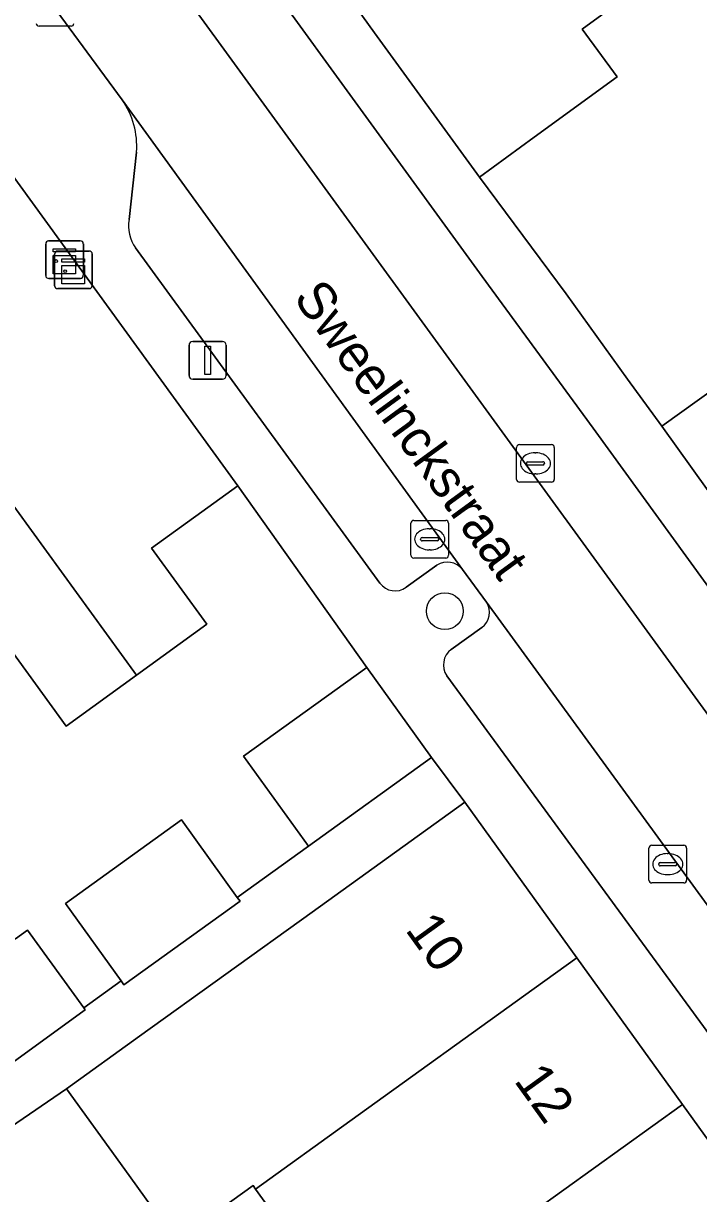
# Model space of a CAD drawing. Extents: x 159817 to 160765, y 380688 to 381638.
# Drawn here: x 159986.43 to 160004.37, y 381261.64 to 381292.74 of the extents above; entities that cross this region are included whole.
import ezdxf

# ---------------------------------------------------------------- set-up
doc = ezdxf.new("R2010")
doc.units = 0
for name, color, linetype in [('IMGEO_Boom', 7, 'Continuous'), ('IMGEO_Erf', 7, 'Continuous'), ('IMGEO_Kast', 7, 'Continuous'), ('IMGEO_Kolk', 7, 'Continuous'), ('IMGEO_Lichtmast', 7, 'Continuous'), ('IMGEO_Muur', 7, 'Continuous'), ('IMGEO_Openbare_ruimte_label', 7, 'Continuous'), ('IMGEO_Pand', 7, 'Continuous'), ('IMGEO_Pand_nummerreeks', 7, 'Continuous'), ('IMGEO_Parkeervlak_open', 7, 'Continuous'), ('IMGEO_Rijbaan_lokaal_open', 7, 'Continuous'), ('IMGEO_Voetpad_open', 7, 'Continuous')]:
    doc.layers.add(name, color=color, linetype=linetype)

msp = doc.modelspace()

# ---------------------------------------------------------------- linework, layer by layer
at = {"layer": 'IMGEO_Boom'}
msp.add_circle((159997.629, 381277.121), 0.489, dxfattribs=at)
at = {"layer": 'IMGEO_Erf'}
for points in [[(160003.758, 381294.399), (160001.277, 381292.589), (160002.202, 381291.321), (160000, 381289.714), (159998.551, 381288.656), (160000.854, 381285.557), (160002.484, 381283.284), (160003.391, 381282.036), (160007.455, 381284.95), (160011.43, 381287.801), (160011.887, 381288.128), (160013.409, 381286.006), (160015.435, 381287.459), (160016.713, 381285.677), (160019.191, 381287.455)], [(159986.225, 381268.414), (159986.544, 381268.646), (159988.034, 381266.576), (159989.03, 381267.293), (159987.548, 381269.352), (159990.632, 381271.572), (159992.114, 381269.514), (159994.006, 381270.876), (159992.283, 381273.269), (159995.552, 381275.622), (159992.128, 381280.454), (159989.838, 381278.792), (159991.302, 381276.775), (159989.435, 381275.42), (159987.567, 381274.065), (159986.123, 381276.055)], [(159993.924, 381259.923), (159992.602, 381261.76), (159992.535, 381261.853), (159990.492, 381260.382), (159989.123, 381262.284), (159987.58, 381264.428), (159980.467, 381259.561)]]:
    msp.add_lwpolyline(points, dxfattribs=at)
at = {"layer": 'IMGEO_Kast'}
for p, q in [((159987.025, 381286.036), (159987.025, 381286.877)), ((159987.025, 381286.877), (159987.025, 381286.036)), ((159987.1, 381286.961), (159987.941, 381286.961)), ((159987.941, 381286.961), (159987.1, 381286.961)), ((159987.338, 381286.691), (159988.179, 381286.691)), ((159988.179, 381286.691), (159987.338, 381286.691)), ((159988.025, 381286.886), (159988.025, 381286.045)), ((159988.025, 381286.045), (159988.025, 381286.886)), ((159987.263, 381285.766), (159987.263, 381286.607)), ((159987.263, 381286.607), (159987.263, 381285.766)), ((159988.263, 381286.616), (159988.263, 381285.775)), ((159988.263, 381285.775), (159988.263, 381286.616)), ((159987.95, 381285.961), (159987.109, 381285.961)), ((159987.109, 381285.961), (159987.95, 381285.961)), ((159988.188, 381285.691), (159987.347, 381285.691)), ((159987.347, 381285.691), (159988.188, 381285.691))]:
    msp.add_line(p, q, dxfattribs=at)
for points in [[(159987.22, 381286.751), (159987.82, 381286.751), (159987.82, 381286.666), (159987.22, 381286.666), (159987.22, 381286.751)], [(159987.22, 381286.576), (159987.82, 381286.576), (159987.82, 381286.087), (159987.22, 381286.087), (159987.22, 381286.576)], [(159987.458, 381286.481), (159988.058, 381286.481), (159988.058, 381286.396), (159987.458, 381286.396), (159987.458, 381286.481)], [(159987.458, 381286.306), (159988.058, 381286.306), (159988.058, 381285.817), (159987.458, 381285.817), (159987.458, 381286.306)]]:
    msp.add_lwpolyline(points, dxfattribs=at)
for centre in [(159987.304, 381286.425), (159987.542, 381286.155)]:
    msp.add_circle(centre, 0.0377, dxfattribs=at)
for centre, start, end in [((159987.103, 381286.883), 92.4484, 184.2845), ((159987.103, 381286.883), 92.4484, 184.2845), ((159987.341, 381286.613), 92.4484, 184.2845), ((159987.341, 381286.613), 92.4484, 184.2845), ((159987.947, 381286.883), 2.4484, 94.2845), ((159987.947, 381286.883), 2.4484, 94.2845), ((159988.185, 381286.613), 2.4484, 94.2845), ((159988.185, 381286.613), 2.4484, 94.2845), ((159987.947, 381286.039), 272.4484, 4.2845), ((159987.947, 381286.039), 272.4484, 4.2845), ((159987.103, 381286.039), 182.4484, 274.2845), ((159987.103, 381286.039), 182.4484, 274.2845), ((159987.341, 381285.769), 182.4484, 274.2845), ((159987.341, 381285.769), 182.4484, 274.2845), ((159988.185, 381285.769), 272.4484, 4.2845), ((159988.185, 381285.769), 272.4484, 4.2845)]:
    msp.add_arc(centre, 0.0779, start, end, dxfattribs=at)
at = {"layer": 'IMGEO_Kolk'}
for p, q in [((159987.7, 381292.666), (159986.848, 381292.666)), ((159999.535, 381280.621), (159999.535, 381281.473)), ((159999.61, 381281.547), (160000.462, 381281.547)), ((160000.536, 381281.473), (160000.536, 381280.621)), ((159999.837, 381281.09), (160000.235, 381281.09)), ((160000.023, 381281.327), (160000.048, 381281.327)), ((159999.794, 381281.041), (159999.794, 381281.053)), ((160000.232, 381281.004), (159999.834, 381281.004)), ((160000.046, 381280.767), (160000.021, 381280.767)), ((160000.278, 381281.053), (160000.278, 381281.041)), ((160000.462, 381280.547), (159999.61, 381280.547)), ((159996.8, 381279.531), (159997.652, 381279.531)), ((159996.725, 381278.605), (159996.725, 381279.457)), ((159997.213, 381279.311), (159997.238, 381279.311)), ((159997.726, 381279.457), (159997.726, 381278.605)), ((159996.984, 381279.025), (159996.984, 381279.037)), ((159997.422, 381278.988), (159997.024, 381278.988)), ((159997.027, 381279.074), (159997.425, 381279.074)), ((159997.468, 381279.037), (159997.468, 381279.025)), ((159997.236, 381278.751), (159997.211, 381278.751)), ((159997.652, 381278.531), (159996.8, 381278.531)), ((160003.05, 381269.971), (160003.05, 381270.823)), ((160003.125, 381270.897), (160003.977, 381270.897)), ((160004.051, 381270.823), (160004.051, 381269.971)), ((160003.538, 381270.677), (160003.563, 381270.677)), ((160003.309, 381270.391), (160003.309, 381270.403)), ((160003.747, 381270.354), (160003.349, 381270.354)), ((160003.352, 381270.44), (160003.75, 381270.44)), ((160003.793, 381270.403), (160003.793, 381270.391)), ((160003.977, 381269.897), (160003.125, 381269.897)), ((160003.561, 381270.117), (160003.536, 381270.117))]:
    msp.add_line(p, q, dxfattribs=at)
for points in [[(159987.7, 381292.666), (159986.848, 381292.666)], [(159999.535, 381280.621), (159999.535, 381281.473)], [(159999.61, 381281.547), (160000.462, 381281.547)], [(160000.536, 381281.473), (160000.536, 381280.621)], [(160000.462, 381280.547), (159999.61, 381280.547)], [(159996.8, 381279.531), (159997.652, 381279.531)], [(159996.725, 381278.605), (159996.725, 381279.457)], [(159997.726, 381279.457), (159997.726, 381278.605)], [(159997.652, 381278.531), (159996.8, 381278.531)], [(160003.05, 381269.971), (160003.05, 381270.823)], [(160003.125, 381270.897), (160003.977, 381270.897)], [(160004.051, 381270.823), (160004.051, 381269.971)], [(160003.977, 381269.897), (160003.125, 381269.897)]]:
    msp.add_lwpolyline(points, dxfattribs=at)
for centre, radius, start, end in [((159986.85, 381292.742), 0.0765, 181.552, 268.448), ((159986.85, 381292.742), 0.0765, 181.552, 268.448), ((159987.698, 381292.742), 0.0765, 271.552, 358.448), ((159987.698, 381292.742), 0.0765, 271.552, 358.448), ((159999.612, 381281.471), 0.0765, 91.552, 178.448), ((159999.612, 381281.471), 0.0765, 91.552, 178.448), ((160000.46, 381281.471), 0.0765, 1.552, 88.448), ((160000.46, 381281.471), 0.0765, 1.552, 88.448), ((159999.834, 381281.05), 0.0403, 85.8775, 175.7526), ((160000.239, 381281.052), 0.0386, 1.7309, 96.639), ((159999.831, 381281.04), 0.0366, 178.938, 274.7102), ((160000.235, 381281.047), 0.043, 264.8664, 352.4533), ((159999.612, 381280.623), 0.0765, 181.552, 268.448), ((159999.612, 381280.623), 0.0765, 181.552, 268.448), ((160000.46, 381280.623), 0.0765, 271.552, 358.448), ((160000.46, 381280.623), 0.0765, 271.552, 358.448), ((159996.802, 381279.455), 0.0765, 91.552, 178.448), ((159996.802, 381279.455), 0.0765, 91.552, 178.448), ((159997.65, 381279.455), 0.0765, 1.552, 88.448), ((159997.65, 381279.455), 0.0765, 1.552, 88.448), ((159997.024, 381279.034), 0.0403, 85.8775, 175.7526), ((159997.021, 381279.024), 0.0366, 178.938, 274.7102), ((159997.425, 381279.031), 0.043, 264.8664, 352.4533), ((159997.429, 381279.036), 0.0386, 1.7309, 96.639), ((159996.802, 381278.607), 0.0765, 181.552, 268.448), ((159996.802, 381278.607), 0.0765, 181.552, 268.448), ((159997.65, 381278.607), 0.0765, 271.552, 358.448), ((159997.65, 381278.607), 0.0765, 271.552, 358.448), ((160003.127, 381270.821), 0.0765, 91.552, 178.448), ((160003.127, 381270.821), 0.0765, 91.552, 178.448), ((160003.975, 381270.821), 0.0765, 1.552, 88.448), ((160003.975, 381270.821), 0.0765, 1.552, 88.448), ((160003.349, 381270.4), 0.0403, 85.8775, 175.7526), ((160003.346, 381270.39), 0.0366, 178.938, 274.7102), ((160003.75, 381270.397), 0.043, 264.8664, 352.4533), ((160003.754, 381270.402), 0.0386, 1.7309, 96.639), ((160003.127, 381269.973), 0.0765, 181.552, 268.448), ((160003.127, 381269.973), 0.0765, 181.552, 268.448), ((160003.975, 381269.973), 0.0765, 271.552, 358.448), ((160003.975, 381269.973), 0.0765, 271.552, 358.448)]:
    msp.add_arc(centre, radius, start, end, dxfattribs=at)
for centre, major_axis, ratio, start_param, end_param in [((160000.022, 381281.047), (-0.387, 0.002), 0.722429, 4.712389, 7.853982), ((160000.047, 381281.047), (-0.39, 0.002), 0.717154, 1.570796, 4.712389), ((159997.212, 381279.031), (-0.387, 0.002), 0.722429, 4.712389, 7.853982), ((159997.237, 381279.031), (-0.39, 0.002), 0.717154, 1.570796, 4.712389), ((160003.537, 381270.397), (-0.387, 0.002), 0.722429, 4.712389, 7.853982), ((160003.562, 381270.397), (-0.39, 0.002), 0.717154, 1.570796, 4.712389)]:
    msp.add_ellipse(centre, major_axis=major_axis, ratio=ratio, start_param=start_param, end_param=end_param, dxfattribs=at)
at = {"layer": 'IMGEO_Lichtmast'}
for p, q in [((159990.832, 381283.386), (159990.832, 381284.186)), ((159990.832, 381284.186), (159990.832, 381283.386)), ((159990.932, 381284.286), (159991.722, 381284.286)), ((159991.722, 381284.286), (159990.932, 381284.286)), ((159991.822, 381284.186), (159991.822, 381283.386)), ((159991.822, 381283.386), (159991.822, 381284.186)), ((159991.722, 381283.286), (159990.932, 381283.286)), ((159990.932, 381283.286), (159991.722, 381283.286))]:
    msp.add_line(p, q, dxfattribs=at)
msp.add_lwpolyline([(159991.252, 381284.161), (159991.402, 381284.161), (159991.402, 381283.411), (159991.252, 381283.411), (159991.252, 381284.161)], dxfattribs=at)
for centre, start, end in [((159990.932, 381284.186), 90, 180), ((159990.932, 381284.186), 90, 180), ((159991.722, 381284.186), 0, 90), ((159991.722, 381284.186), 360, 90), ((159990.932, 381283.386), 180, 270), ((159990.932, 381283.386), 180, 270), ((159991.722, 381283.386), 270, 0), ((159991.722, 381283.386), 270, 0)]:
    msp.add_arc(centre, 0.1, start, end, dxfattribs=at)
at = {"layer": 'IMGEO_Muur'}
for points in [[(159998.551, 381288.656), (160000.854, 381285.557)], [(159995.552, 381275.622), (159992.128, 381280.454)]]:
    msp.add_lwpolyline(points, dxfattribs=at)
at = {"layer": 'IMGEO_Pand'}
for points in [[(160002.092, 381296.712), (160002.012, 381296.823), (160000, 381299.618), (159997.826, 381302.638), (159994.096, 381299.916), (159995.499, 381297.994), (159993.163, 381296.289), (159993.076, 381296.226), (159995.756, 381292.487), (159998.551, 381288.656), (160000, 381289.714), (160002.202, 381291.321), (160001.277, 381292.589), (160003.758, 381294.399), (160002.988, 381295.468)], [(159989.435, 381275.42), (159991.302, 381276.775), (159989.838, 381278.792), (159992.128, 381280.454), (159986.019, 381288.871), (159981.862, 381285.854)], [(160016.587, 381285.587), (160016.713, 381285.677), (160015.435, 381287.459), (160013.409, 381286.006), (160011.887, 381288.128), (160011.43, 381287.801), (160007.455, 381284.95), (160003.391, 381282.036), (160006.192, 381278.13)], [(159989.435, 381275.42), (159981.862, 381285.854), (159977.802, 381282.908), (159982.182, 381276.873), (159983.93, 381274.464), (159986.123, 381276.055), (159987.567, 381274.065)], [(159997.275, 381273.229), (159995.552, 381275.622), (159992.283, 381273.269), (159994.006, 381270.876)], [(160001.134, 381267.906), (160000, 381269.482), (159998.157, 381272.042), (159994.1, 381269.121), (159989.52, 381265.824), (159987.58, 381264.428), (159989.123, 381262.284), (159990.492, 381260.382), (159992.535, 381261.853), (159992.602, 381261.76), (159995.105, 381263.563), (160000, 381267.089)], [(159987.548, 381269.352), (159989.03, 381267.293), (159989.103, 381267.192), (159992.187, 381269.412), (159992.114, 381269.514), (159990.632, 381271.572)], [(159988.034, 381266.576), (159986.544, 381268.646), (159986.225, 381268.414), (159980.527, 381264.278), (159982.008, 381262.237), (159982.063, 381262.161), (159987.953, 381266.437), (159988.072, 381266.524)], [(160003.94, 381264.009), (160001.134, 381267.906), (160000, 381267.089), (159995.105, 381263.563), (159992.602, 381261.76), (159993.924, 381259.923), (159991.926, 381258.485), (159993.409, 381256.425), (160000, 381261.171)], [(160003.94, 381264.009), (160000, 381261.171), (159993.409, 381256.425), (159994.594, 381254.779), (159996.673, 381256.276), (159998.132, 381254.249), (159998.013, 381253.984), (159998.159, 381253.781), (160000, 381255.107), (160000.792, 381255.677), (160006.815, 381260.015)]]:
    msp.add_lwpolyline(points, close=True, dxfattribs=at)
at = {"layer": 'IMGEO_Parkeervlak_open'}
for points in [[(159989.181, 381295.608), (160012.477, 381263.554)], [(159998.623, 381286.018), (159992.724, 381294.136)], [(159998.096, 381278.226), (159989.058, 381290.708)], [(159989.437, 381289.321), (159989.239, 381287.531)], [(159989.415, 381286.773), (159995.9, 381277.867)], [(160001.567, 381281.987), (159998.623, 381286.018)], [(160012.168, 381267.377), (160001.567, 381281.987)], [(159996.604, 381277.754), (159997.416, 381278.343)], [(160010.079, 381261.792), (159998.733, 381277.36)], [(159998.614, 381276.682), (159997.799, 381276.104)], [(159997.679, 381275.402), (160006.55, 381263.277)]]:
    msp.add_lwpolyline(points, dxfattribs=at)
for centre, radius, start, end in [((159987.294, 381289.481), 2.149, 355.7356, 34.8306), ((159990.274, 381287.372), 1.047, 171.264, 214.8798), ((159997.692, 381277.911), 0.513, 37.9295, 122.5451), ((159996.309, 381278.167), 0.507, 216.2522, 305.5101), ((159998.306, 381277.086), 0.508, 307.3612, 32.7289), ((159998.102, 381275.691), 0.512, 126.2599, 214.3393)]:
    msp.add_arc(centre, radius, start, end, dxfattribs=at)
at = {"layer": 'IMGEO_Rijbaan_lokaal_open'}
msp.add_lwpolyline([(159989.181, 381295.608), (159989.023, 381295.839), (159986.615, 381294.042), (159989.058, 381290.708), (159998.096, 381278.226), (159998.733, 381277.36), (160010.079, 381261.792), (160012.477, 381263.554)], close=True, dxfattribs=at)
at = {"layer": 'IMGEO_Voetpad_open'}
for points in [[(160023.169, 381261.054), (160018.73, 381263.121), (160018.356, 381264.659), (160016.78, 381266.022), (160014.618, 381266.378), (160011.792, 381270.319), (160008.993, 381274.224), (160006.192, 381278.13), (160003.391, 381282.036), (160002.484, 381283.284), (160000.854, 381285.557), (159998.551, 381288.656), (159995.756, 381292.487), (159993.076, 381296.226), (159991.398, 381298.567), (159988.478, 381303.94)], [(159989.058, 381290.708), (159986.615, 381294.042), (159985.401, 381295.681)], [(159992.724, 381294.136), (159998.623, 381286.018), (160001.567, 381281.987), (160012.168, 381267.377)], [(159989.239, 381287.531), (159989.437, 381289.321)], [(159986.019, 381288.871), (159992.128, 381280.454), (159995.552, 381275.622), (159997.275, 381273.229), (159998.157, 381272.042), (160000, 381269.482), (160001.134, 381267.906), (160003.94, 381264.009), (160006.815, 381260.015), (160009.505, 381256.28), (160013.998, 381254.187), (160014.359, 381254.019), (160018.402, 381252.136), (160018.62, 381252.034), (160022.807, 381250.084), (160022.944, 381250.02), (160027.212, 381248.033), (160030.548, 381246.479), (160031.617, 381245.981), (160033.032, 381245.322), (160036.021, 381243.93), (160040.426, 381241.878), (160041.843, 381241.188), (160046.955, 381238.804)], [(159995.9, 381277.867), (159989.415, 381286.773)], [(159997.416, 381278.343), (159996.604, 381277.754)], [(159998.733, 381277.36), (159998.096, 381278.226)], [(159997.799, 381276.104), (159998.614, 381276.682)], [(160006.55, 381263.277), (159997.679, 381275.402)], [(159980.467, 381259.561), (159987.58, 381264.428), (159989.52, 381265.824), (159994.1, 381269.121), (159998.157, 381272.042), (159997.275, 381273.229), (159994.006, 381270.876), (159992.114, 381269.514), (159992.187, 381269.412), (159989.103, 381267.192), (159989.03, 381267.293), (159988.034, 381266.576), (159988.072, 381266.524), (159987.953, 381266.437), (159982.063, 381262.161)]]:
    msp.add_lwpolyline(points, dxfattribs=at)
for centre, radius, start, end in [((159987.294, 381289.481), 2.149, 355.7356, 34.8306), ((159990.274, 381287.372), 1.047, 171.264, 214.8798), ((159997.692, 381277.911), 0.513, 37.9295, 122.5451), ((159996.309, 381278.167), 0.507, 216.2522, 305.5101), ((159998.306, 381277.086), 0.508, 307.3612, 32.7289), ((159998.102, 381275.691), 0.512, 126.2599, 214.3393)]:
    msp.add_arc(centre, radius, start, end, dxfattribs=at)

# ---------------------------------------------------------------- texts
at = {"layer": 'IMGEO_Openbare_ruimte_label'}
msp.add_text('Sweelinckstraat', height=1, rotation=306.0906, dxfattribs=at).set_placement((159993.582, 381285.442))
at = {"layer": 'IMGEO_Pand_nummerreeks'}
for s, rotation, p in [('10', 305.7505, (159996.556, 381268.652)), ('12', 305.7501, (159999.445, 381264.641))]:
    msp.add_text(s, height=1, rotation=rotation, dxfattribs=at).set_placement(p)

doc.saveas('drawing.dxf')
